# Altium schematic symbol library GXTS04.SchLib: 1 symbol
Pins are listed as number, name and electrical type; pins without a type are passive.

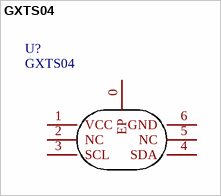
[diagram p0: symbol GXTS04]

## GXTS04
designator U?
footprint QFN6-EP(2*2*0.75) P=0.5
pins: 0 EP, 1 VCC, 2 NC, 3 SCL, 4 SDA, 5 NC, 6 GND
